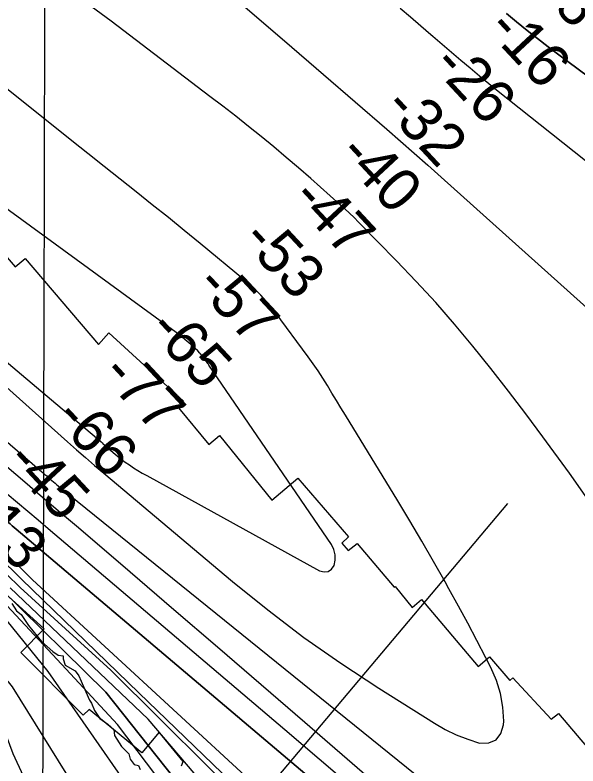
# Model space of a CAD drawing. Extents: x 3172231 to 3210228, y 940198 to 965780.
# Drawn here: x 3192098 to 3192968, y 946666 to 947827 of the extents above; entities that cross this region are included whole.
import ezdxf

# ---------------------------------------------------------------- set-up
doc = ezdxf.new("R2010")
doc.units = 0
for name, color, linetype in [('V-GRID-MAJR', 7, 'Continuous'), ('V-RIVR-EDGE', 7, 'Continuous'), ('V-RIVR-RANG', 7, 'Continuous'), ('V-RRAP-RVMT', 7, 'Continuous'), ('V-TOPO-DPTH', 7, 'Continuous'), ('V-TOPO-MAJR', 7, 'Continuous'), ('V-TOPO-MINR', 7, 'Continuous'), ('V-TOPO-WATR', 7, 'Continuous')]:
    doc.layers.add(name, color=color, linetype=linetype)

msp = doc.modelspace()

# ---------------------------------------------------------------- linework, layer by layer
at = {"layer": 'V-GRID-MAJR'}
msp.add_spline([(3192138.65, 945691.144), (3192153.634, 951750.897), (3192168.626, 957814.116), (3192183.618, 963877.385), (3192183.626, 963880.798)], degree=3, dxfattribs=at)
at = {"layer": 'V-RIVR-EDGE'}
msp.add_lwpolyline([(3192093.058, 946916.984), (3192099.772, 946905.558), (3192107.018, 946899.835), (3192118.387, 946883.211), (3192138.552, 946858.267), (3192156.146, 946842.665), (3192164.43, 946836.94), (3192172.208, 946836.402), (3192172.197, 946831.734), (3192175.284, 946821.873), (3192190.821, 946813.018), (3192196.506, 946805.224), (3192207.336, 946780.304), (3192213.01, 946767.843), (3192216.11, 946763.167), (3192220.749, 946751.746), (3192229.016, 946739.279), (3192241.441, 946730.431), (3192250.756, 946722.11), (3192251.77, 946712.773), (3192262.62, 946696.15), (3192273.483, 946684.713), (3192275.537, 946676.41), (3192281.74, 946668.097), (3192288.478, 946666.525), (3192291.056, 946660.295)], dxfattribs=at)
at = {"layer": 'V-RIVR-RANG'}
msp.add_line((3192112.067, 946184.869), (3192859.884, 947071.645), dxfattribs=at)
at = {"layer": 'V-RRAP-RVMT'}
for p, q in [((3192016.837, 947532.321), (3192097.733, 947437.716)), ((3192097.733, 947437.716), (3192113.403, 947450.51)), ((3192113.403, 947450.51), (3192226.593, 947317.523)), ((3192226.593, 947317.523), (3192242.664, 947335.324)), ((3192242.664, 947335.324), (3192358.272, 947229.722)), ((3192358.272, 947229.722), (3192350.563, 947219.59)), ((3192350.563, 947219.59), (3192397.48, 947162.954)), ((3192397.48, 947162.954), (3192413.942, 947176.96)), ((3192413.942, 947176.96), (3192494.686, 947077.055)), ((3192494.686, 947077.055), (3192535.118, 947110.815)), ((3192535.118, 947110.815), (3192613.558, 947020)), ((3192613.558, 947020), (3192603.258, 947010.595)), ((3192603.258, 947010.595), (3192612.92, 946998.905)), ((3192612.92, 946998.905), (3192626.929, 947009.592)), ((3192626.929, 947009.592), (3192684.117, 946942.488)), ((3192142.85, 946878.104), (3192076.467, 946938.134)), ((3192684.117, 946942.488), (3192685.424, 946943.503)), ((3192685.424, 946943.503), (3192711.798, 946910.78)), ((3192711.798, 946910.78), (3192726.251, 946923.33)), ((3192726.251, 946923.33), (3192813.805, 946819.57)), ((3192106.615, 946841.301), (3192142.85, 946878.104)), ((3192203.296, 946744.434), (3192106.615, 946841.301)), ((3192813.805, 946819.57), (3192831.383, 946834.488)), ((3192831.383, 946834.488), (3192862.809, 946797.983)), ((3192862.809, 946797.983), (3192867.431, 946802.249)), ((3192867.431, 946802.249), (3192926.955, 946738.021)), ((3192212.274, 946753.327), (3192203.296, 946744.434)), ((3192294.014, 946686.38), (3192212.274, 946753.327)), ((3192926.955, 946738.021), (3192938.075, 946746.946)), ((3192938.075, 946746.946), (3193025.982, 946643.213)), ((3192320.819, 946718.1), (3192294.014, 946686.38)), ((3192357.79, 946672.541), (3192320.819, 946718.1)), ((3192355.33, 946665.852), (3192357.79, 946672.541))]:
    msp.add_line(p, q, dxfattribs=at)
at = {"layer": 'V-TOPO-DPTH'}
for points in [[(3190795.989, 948054.391), (3191058.755, 947768.507), (3191064.568, 947762.315), (3191070.468, 947756.208), (3191076.496, 947750.229), (3191082.61, 947744.334), (3191635.142, 947374.634), (3191679.916, 947341.25), (3191724.064, 947307.079), (3191767.273, 947271.729), (3191809.857, 947235.592), (3192012.278, 947059.062), (3192038.925, 947035.354), (3192065.252, 947011.301), (3192091.097, 946986.732), (3192116.621, 946961.819), (3192125.015, 946953.462)], [(3192125.015, 946953.462), (3192116.621, 946961.819), (3192091.097, 946986.732), (3192065.252, 947011.301), (3192038.925, 947035.354), (3192012.278, 947059.062), (3191809.857, 947235.592), (3191767.273, 947271.729), (3191724.064, 947307.079), (3191679.916, 947341.25), (3191635.142, 947374.634), (3191082.61, 947744.334), (3191076.496, 947750.229), (3191070.468, 947756.208), (3191064.568, 947762.315), (3191058.755, 947768.507), (3190795.989, 948054.391)], [(3192105.596, 946941.56), (3192084.673, 946962.391), (3192067.073, 946979.569), (3192049.253, 946996.51), (3192031.1, 947013.095), (3192012.726, 947029.442), (3191871.98, 947152.187), (3191843.196, 947176.588), (3191813.973, 947200.437), (3191784.094, 947223.457), (3191753.777, 947245.924), (3191722.828, 947267.51), (3191691.477, 947288.475), (3191659.523, 947308.509), (3191081.962, 947712.367), (3191066.909, 947726.551), (3191052.087, 947740.967), (3191037.61, 947755.73), (3191023.364, 947770.724), (3190904.893, 947898.407)], [(3190904.893, 947898.407), (3191023.364, 947770.724), (3191037.61, 947755.73), (3191052.087, 947740.967), (3191066.909, 947726.551), (3191081.962, 947712.367), (3191659.523, 947308.509), (3191691.477, 947288.475), (3191722.828, 947267.51), (3191753.777, 947245.924), (3191784.094, 947223.457), (3191813.973, 947200.437), (3191843.196, 947176.588), (3191871.98, 947152.187), (3192012.726, 947029.442), (3192031.1, 947013.095), (3192049.253, 946996.51), (3192067.073, 946979.569), (3192084.673, 946962.391), (3192105.596, 946941.56)], [(3193302.766, 947345.6), (3192859.707, 947696.97), (3192844.993, 947708.748), (3192830.353, 947720.615), (3192815.822, 947732.616), (3192801.363, 947744.705), (3192786.981, 947756.888), (3192772.629, 947769.105), (3192758.321, 947781.373), (3192744.043, 947793.677), (3192740.94, 947796.36), (3192725.075, 947809.964), (3192709.135, 947823.477), (3192693.08, 947836.855)], [(3193302.766, 947345.6), (3192859.707, 947696.97), (3192844.993, 947708.748), (3192830.353, 947720.615), (3192815.822, 947732.616), (3192801.363, 947744.705), (3192786.981, 947756.888), (3192772.629, 947769.105), (3192758.321, 947781.373), (3192744.043, 947793.677), (3192740.94, 947796.36), (3192725.075, 947809.964), (3192709.135, 947823.477), (3192693.08, 947836.855)], [(3193177.589, 947588.044), (3192938.523, 947765.434), (3192922.019, 947777.864), (3192905.637, 947790.451), (3192889.437, 947803.272), (3192873.359, 947816.249), (3192857.45, 947829.435)], [(3192857.45, 947829.435), (3192873.359, 947816.249), (3192889.437, 947803.272), (3192905.637, 947790.451), (3192922.019, 947777.864), (3192938.523, 947765.434), (3193177.589, 947588.044)], [(3191034.173, 947827.902), (3191041.949, 947819.8), (3191049.938, 947811.772), (3191058.11, 947803.943), (3191066.559, 947796.413), (3191075.192, 947789.082), (3191084.105, 947782.101), (3191748.04, 947324.383), (3192006.622, 947110.179), (3192014.989, 947103.225), (3192023.341, 947096.252), (3192031.67, 947089.253), (3192039.983, 947082.235), (3192048.29, 947075.208), (3192056.601, 947068.187), (3192064.921, 947061.176), (3192073.246, 947054.171), (3192086.789, 947042.788), (3192090.015, 947040.073), (3192093.24, 947037.357), (3192096.461, 947034.637), (3192099.681, 947031.915), (3192938.779, 946321.755)], [(3192938.779, 946321.755), (3192099.681, 947031.915), (3192096.461, 947034.637), (3192093.24, 947037.357), (3192090.015, 947040.073), (3192086.789, 947042.788), (3192073.246, 947054.171), (3192064.921, 947061.176), (3192056.601, 947068.187), (3192048.29, 947075.208), (3192039.983, 947082.235), (3192031.67, 947089.253), (3192023.341, 947096.252), (3192014.989, 947103.225), (3192006.622, 947110.179), (3191748.04, 947324.383), (3191084.105, 947782.101), (3191075.192, 947789.082), (3191066.559, 947796.413), (3191058.11, 947803.943), (3191049.938, 947811.772), (3191041.949, 947819.8), (3191034.173, 947827.902)], [(3192085.816, 947086.649), (3192101.652, 947073.241), (3192117.484, 947059.828), (3192133.309, 947046.406), (3192149.13, 947032.979), (3192514.85, 946722.415), (3192596.158, 946652.773)], [(3192085.816, 947086.649), (3192101.652, 947073.241), (3192117.484, 947059.828), (3192133.309, 947046.406), (3192149.13, 947032.979), (3192514.85, 946722.415), (3192596.158, 946652.773)], [(3192125.015, 946953.462), (3192460.326, 946644.437), (3192753.916, 946312.397), (3192794.718, 946219.197), (3192790.938, 946185.676), (3192775.977, 946144.723), (3192749.876, 946122.415), (3192727.511, 946107.551), (3192708.876, 946096.406), (3192686.499, 946074.092), (3192664.115, 946048.052), (3192652.89, 946014.543), (3192658.947, 945963.859)], [(3192658.947, 945963.859), (3192652.89, 946014.543), (3192664.115, 946048.052), (3192686.499, 946074.092), (3192708.876, 946096.406), (3192727.511, 946107.551), (3192749.876, 946122.415), (3192775.977, 946144.723), (3192790.938, 946185.676), (3192794.718, 946219.197), (3192753.916, 946312.397), (3192460.326, 946644.437), (3192125.015, 946953.462)], [(3192454.597, 945730.763), (3192433.513, 945838.931), (3192413.857, 945970.211), (3192408.07, 946075.617), (3192400.398, 946242.672), (3192384.69, 946358.038), (3192366.954, 946449.543), (3192323.384, 946543.08), (3192273.844, 946632.65), (3192148.926, 946811.832), (3192048.178, 946936.112)], [(3192556.965, 945873.249), (3192535.012, 945918.306), (3192525.143, 945960.083), (3192529.261, 946045.586), (3192539.308, 946111.193), (3192553.314, 946166.851), (3192559.38, 946228.487), (3192561.44, 946272.233), (3192559.519, 946312.008), (3192553.616, 946347.813), (3192527.864, 946399.56), (3192508.058, 946441.353), (3192448.554, 946515.031), (3192238.314, 946779.866), (3192074.996, 946940.791)], [(3192074.996, 946940.791), (3192238.314, 946779.866), (3192448.554, 946515.031), (3192508.058, 946441.353), (3192527.864, 946399.56), (3192553.616, 946347.813), (3192559.519, 946312.008), (3192561.44, 946272.233), (3192559.38, 946228.487), (3192553.314, 946166.851), (3192539.308, 946111.193), (3192529.261, 946045.586), (3192525.143, 945960.083), (3192535.012, 945918.306), (3192556.965, 945873.249)], [(3192596.457, 945900.913), (3192580.371, 945940.634), (3192574.484, 945986.382), (3192582.504, 946028.129), (3192592.482, 946051.975), (3192608.442, 946087.744), (3192630.358, 946119.525), (3192680.127, 946167.168), (3192696.1, 946210.891), (3192696.163, 946248.674), (3192678.345, 946290.465), (3192638.696, 946352.178), (3192581.193, 946433.806), (3192472.136, 946589.099), (3192245.929, 946814.188), (3192105.596, 946941.56)], [(3192105.596, 946941.56), (3192245.929, 946814.188), (3192472.136, 946589.099), (3192581.193, 946433.806), (3192638.696, 946352.178), (3192678.345, 946290.465), (3192696.163, 946248.674), (3192696.1, 946210.891), (3192680.127, 946167.168), (3192630.358, 946119.525), (3192608.442, 946087.744), (3192592.482, 946051.975), (3192582.504, 946028.129), (3192574.484, 945986.382), (3192580.371, 945940.634), (3192596.457, 945900.913)]]:
    msp.add_lwpolyline(points, dxfattribs=at)
at = {"layer": 'V-TOPO-MAJR'}
for points in [[(3192453.461, 947839.288), (3192514.267, 947787.185), (3192574.924, 947734.907), (3192672.516, 947650.427), (3192693.708, 947631.986), (3192714.836, 947613.473), (3192735.868, 947594.85), (3192756.836, 947576.155), (3193206.826, 947172.85)], [(3192985.427, 946352.41), (3192545.757, 946733.188), (3192478.4, 946791.404), (3192410.965, 946849.529), (3192343.413, 946907.518), (3192275.783, 946965.417), (3192195.71, 947033.829), (3192168.058, 947057.452), (3192140.404, 947081.075), (3192112.75, 947104.696), (3192085.094, 947128.316)]]:
    msp.add_lwpolyline(points, dxfattribs=at)
at = {"layer": 'V-TOPO-MINR'}
for points in [[(3190795.989, 948054.391), (3191058.755, 947768.507), (3191064.568, 947762.315), (3191070.468, 947756.208), (3191076.496, 947750.229), (3191082.61, 947744.334), (3191635.142, 947374.634), (3191679.916, 947341.25), (3191724.064, 947307.079), (3191767.273, 947271.729), (3191809.857, 947235.592), (3192012.278, 947059.062), (3192038.925, 947035.354), (3192065.252, 947011.301), (3192091.097, 946986.732), (3192116.621, 946961.819), (3192125.015, 946953.462)], [(3191423.567, 947848.409), (3192230.35, 947167.61), (3192232.91, 947165.244), (3192233.775, 947164.469), (3192249.722, 947150.348), (3192255.695, 947145.275), (3192261.798, 947140.372), (3192268.098, 947135.724), (3192274.528, 947131.246), (3192281.109, 947126.98), (3192287.757, 947122.826), (3192294.507, 947118.839), (3192301.324, 947114.964), (3192568.789, 946967.335), (3192575.738, 946965.832), (3192581.908, 946966.394), (3192586.91, 946970.051), (3192591.132, 946975.772), (3192592.827, 946984.259), (3192592.958, 946992.546), (3192590.742, 947000.532), (3192586.96, 947008.317), (3192397.648, 947285.441), (3192396.655, 947286.894), (3192395.662, 947288.347), (3192393.676, 947291.253), (3192391.639, 947294.12), (3192389.499, 947296.912), (3192384.462, 947303.244), (3192383.51, 947304.383), (3192380.412, 947307.573), (3192372.832, 947314.473), (3192369.698, 947317.28), (3192366.535, 947320.052), (3192363.326, 947322.771), (3192360.088, 947325.457), (3192356.825, 947328.113), (3192353.559, 947330.765), (3192350.288, 947333.412), (3192347.015, 947336.056), (3191437.622, 947999.666)], [(3190880.337, 947944.43), (3191041.855, 947769.581), (3191051.689, 947759.172), (3191061.675, 947748.915), (3191071.889, 947738.884), (3191082.254, 947729.005), (3191650.711, 947341.141), (3191683.208, 947318.366), (3191694.589, 947310.147), (3191732.069, 947282.287), (3191769.016, 947253.755), (3191805.164, 947224.218), (3191840.779, 947194.01), (3192012.502, 947044.249), (3192035.012, 947024.222), (3192057.251, 947003.904), (3192079.083, 946983.15), (3192100.643, 946962.105), (3192107.839, 946954.941)], [(3190904.893, 947898.407), (3191023.364, 947770.724), (3191037.61, 947755.73), (3191052.087, 947740.967), (3191066.909, 947726.551), (3191081.962, 947712.367), (3191659.523, 947308.509), (3191691.477, 947288.475), (3191722.828, 947267.51), (3191753.777, 947245.924), (3191784.094, 947223.457), (3191813.973, 947200.437), (3191843.196, 947176.588), (3191871.98, 947152.187), (3192012.726, 947029.442), (3192031.1, 947013.095), (3192049.253, 946996.51), (3192067.073, 946979.569), (3192084.673, 946962.391), (3192105.596, 946941.56)], [(3192986.487, 947073.752), (3192954.948, 947118.55), (3192913.969, 947174.685), (3192887.561, 947210.253), (3192860.777, 947245.531), (3192833.427, 947280.372), (3192805.7, 947314.922), (3192777.241, 947348.852), (3192748.183, 947382.246), (3192718.227, 947414.838), (3192687.673, 947446.894), (3192629.006, 947506.79), (3192621.96, 947513.829), (3192614.815, 947520.764), (3192607.521, 947527.541), (3192600.127, 947534.214), (3192555.027, 947574.037), (3192536.072, 947590.561), (3192516.98, 947606.924), (3192497.681, 947623.043), (3192478.246, 947639.001), (3192458.635, 947654.744), (3192438.928, 947670.365), (3192419.076, 947685.801), (3192399.128, 947701.115), (3192246.37, 947817.255), (3192199.899, 947851.786)], [(3193302.766, 947345.6), (3192859.707, 947696.97), (3192844.993, 947708.748), (3192830.353, 947720.615), (3192815.822, 947732.616), (3192801.363, 947744.705), (3192786.981, 947756.888), (3192772.629, 947769.105), (3192758.321, 947781.373), (3192744.043, 947793.677), (3192740.94, 947796.36), (3192725.075, 947809.964), (3192709.135, 947823.477), (3192693.08, 947836.855)], [(3193177.589, 947588.044), (3192938.523, 947765.434), (3192922.019, 947777.864), (3192905.637, 947790.451), (3192889.437, 947803.272), (3192873.359, 947816.249), (3192857.45, 947829.435)], [(3191034.173, 947827.902), (3191041.949, 947819.8), (3191049.938, 947811.772), (3191058.11, 947803.943), (3191066.559, 947796.413), (3191075.192, 947789.082), (3191084.105, 947782.101), (3191748.04, 947324.383), (3192006.622, 947110.179), (3192014.989, 947103.225), (3192023.341, 947096.252), (3192031.67, 947089.253), (3192039.983, 947082.235), (3192048.29, 947075.208), (3192056.601, 947068.187), (3192064.921, 947061.176), (3192073.246, 947054.171), (3192086.789, 947042.788), (3192090.015, 947040.073), (3192093.24, 947037.357), (3192096.461, 947034.637), (3192099.681, 947031.915), (3192938.779, 946321.755)], [(3191970.529, 947352.931), (3192178.808, 947167.071), (3192192.713, 947154.773), (3192206.69, 947142.558), (3192220.775, 947130.468), (3192234.932, 947118.46), (3192434.143, 946951.012), (3192488.679, 946907.064), (3192544.351, 946864.675), (3192601.728, 946824.623), (3192660.241, 946786.129), (3192746.47, 946731.924), (3192763.067, 946722.482), (3192780.11, 946714.053), (3192797.826, 946707.148), (3192815.989, 946701.257), (3192830.178, 946701.858), (3192841.589, 946706.139), (3192848.834, 946715.94), (3192853.301, 946729.421), (3192853.344, 946735.006), (3192851.925, 946756.617), (3192848.484, 946777.744), (3192842.009, 946798.148), (3192833.512, 946818.069), (3192825.874, 946832.863), (3192811.848, 946859.738), (3192797.666, 946886.53), (3192783.25, 946913.196), (3192768.677, 946939.779), (3192762.806, 946950.379), (3192744.972, 946982.077), (3192726.861, 947013.613), (3192708.333, 947044.907), (3192689.527, 947076.038), (3192608.596, 947208.028), (3192601.599, 947219.494), (3192594.634, 947230.98), (3192587.717, 947242.494), (3192580.833, 947254.028), (3192573.797, 947265.459), (3192566.526, 947276.733), (3192558.902, 947287.772), (3192551.043, 947298.653), (3192499.779, 947367.321), (3192488.993, 947380.735), (3192477.613, 947393.583), (3192465.341, 947405.583), (3192452.476, 947417.016), (3192384.045, 947473.564), (3192359.485, 947493.722), (3192334.835, 947513.77), (3192310.053, 947533.653), (3192285.181, 947553.427), (3192260.258, 947573.136), (3192235.355, 947592.872), (3192210.483, 947612.645), (3192185.63, 947632.443), (3192068.722, 947725.721)], [(3191847.426, 947372.385), (3192135.776, 947123.763), (3192138.521, 947121.391), (3192141.261, 947119.015), (3192143.996, 947116.633), (3192146.727, 947114.246), (3192149.762, 947111.603), (3192152.21, 947109.496), (3192154.673, 947107.407), (3192157.147, 947105.33), (3192159.633, 947103.268), (3192162.125, 947101.213), (3192164.626, 947099.169), (3192167.133, 947097.133), (3192810.081, 946577.224)], [(3192085.816, 947086.649), (3192101.652, 947073.241), (3192117.484, 947059.828), (3192133.309, 947046.406), (3192149.13, 947032.979), (3192514.85, 946722.415), (3192596.158, 946652.773)], [(3192624.36, 945925.872), (3192611.871, 945977.359), (3192615.7, 946040.682), (3192641.813, 946070.441), (3192664.209, 946103.931), (3192701.479, 946126.221), (3192749.945, 946163.393), (3192759.718, 946220.728), (3192742.666, 946263.987), (3192620.044, 946413.203), (3192475.145, 946599.709), (3192289.277, 946778.832), (3192107.839, 946954.941)], [(3192658.947, 945963.859), (3192652.89, 946014.543), (3192664.115, 946048.052), (3192686.499, 946074.092), (3192708.876, 946096.406), (3192727.511, 946107.551), (3192749.876, 946122.415), (3192775.977, 946144.723), (3192790.938, 946185.676), (3192794.718, 946219.197), (3192753.916, 946312.397), (3192460.326, 946644.437), (3192125.015, 946953.462)], [(3192454.597, 945730.763), (3192433.513, 945838.931), (3192413.857, 945970.211), (3192408.07, 946075.617), (3192400.398, 946242.672), (3192384.69, 946358.038), (3192366.954, 946449.543), (3192323.384, 946543.08), (3192273.844, 946632.65), (3192148.926, 946811.832), (3192048.178, 946936.112)], [(3192492.143, 945790.417), (3192485.226, 945860.719), (3192481.334, 945910.441), (3192481.45, 945980.042), (3192479.629, 946079.475), (3192479.821, 946194.814), (3192470.026, 946280.34), (3192460.174, 946332.06), (3192430.533, 946435.517), (3192375.097, 946564.868), (3192331.48, 946630.565), (3192256.119, 946730.121), (3192176.759, 946815.763), (3192063.442, 946936.674)], [(3192567.388, 945896.273), (3192554.927, 945942.136), (3192551.038, 945993.846), (3192557.104, 946055.482), (3192577.062, 946105.164), (3192589.06, 946148.894), (3192597.08, 946190.641), (3192599.141, 946234.387), (3192599.214, 946278.136), (3192597.336, 946343.763), (3192583.472, 946373.615), (3192559.691, 946415.415), (3192490.299, 946518.938), (3192303.833, 946737.996), (3192090.281, 946941.191)], [(3192596.457, 945900.913), (3192580.371, 945940.634), (3192574.484, 945986.382), (3192582.504, 946028.129), (3192592.482, 946051.975), (3192608.442, 946087.744), (3192630.358, 946119.525), (3192680.127, 946167.168), (3192696.1, 946210.891), (3192696.163, 946248.674), (3192678.345, 946290.465), (3192638.696, 946352.178), (3192581.193, 946433.806), (3192472.136, 946589.099), (3192245.929, 946814.188), (3192105.596, 946941.56)], [(3192384.031, 945691.507), (3192369.742, 945737.618), (3192326.265, 945886.836), (3192278.809, 946034.072), (3192219.587, 946276.78), (3192190.019, 946423.986), (3192142.579, 946581.165), (3192095.05, 946684.652), (3192051.516, 946800.063), (3192025.744, 946839.878), (3191992.769, 946879.29)], [(3192012.814, 946887.224), (3192093.235, 946788.062), (3192176.49, 946654.687), (3192251.812, 946531.268), (3192301.315, 946419.823), (3192324.98, 946308.422), (3192340.702, 946201.011), (3192360.329, 946051.833), (3192370.137, 945974.261), (3192387.866, 945878.779), (3192399.652, 945795.238), (3192413.455, 945729.591), (3192423.115, 945691.168)]]:
    msp.add_lwpolyline(points, dxfattribs=at)
at = {"layer": 'V-TOPO-WATR'}
msp.add_lwpolyline([(3192556.965, 945873.249), (3192535.012, 945918.306), (3192525.143, 945960.083), (3192529.261, 946045.586), (3192539.308, 946111.193), (3192553.314, 946166.851), (3192559.38, 946228.487), (3192561.44, 946272.233), (3192559.519, 946312.008), (3192553.616, 946347.813), (3192527.864, 946399.56), (3192508.058, 946441.353), (3192448.554, 946515.031), (3192238.314, 946779.866), (3192074.996, 946940.791)], dxfattribs=at)

# ---------------------------------------------------------------- texts
at = {"layer": 'V-RIVR-RANG'}
for s, p in [('-8', (3192908.669, 947861.028)), ('-16', (3192825.261, 947803.862)), ('-26', (3192740.415, 947748.24)), ('-32', (3192664.917, 947682.578)), ('-40', (3192595.35, 947610.546)), ('-47', (3192522.546, 947541.989)), ('-53', (3192445.611, 947477.872)), ('-57', (3192374.426, 947407.577)), ('-65', (3192301.443, 947339.213)), ('-77', (3192228.822, 947270.463)), ('-66', (3192155.839, 947202.1)), ('-45', (3192081.418, 947135.28)), ('-13', (3192016.346, 947058.421))]:
    msp.add_text(s, height=67, rotation=312.955556, dxfattribs=at).set_placement(p)

doc.saveas('drawing.dxf')
